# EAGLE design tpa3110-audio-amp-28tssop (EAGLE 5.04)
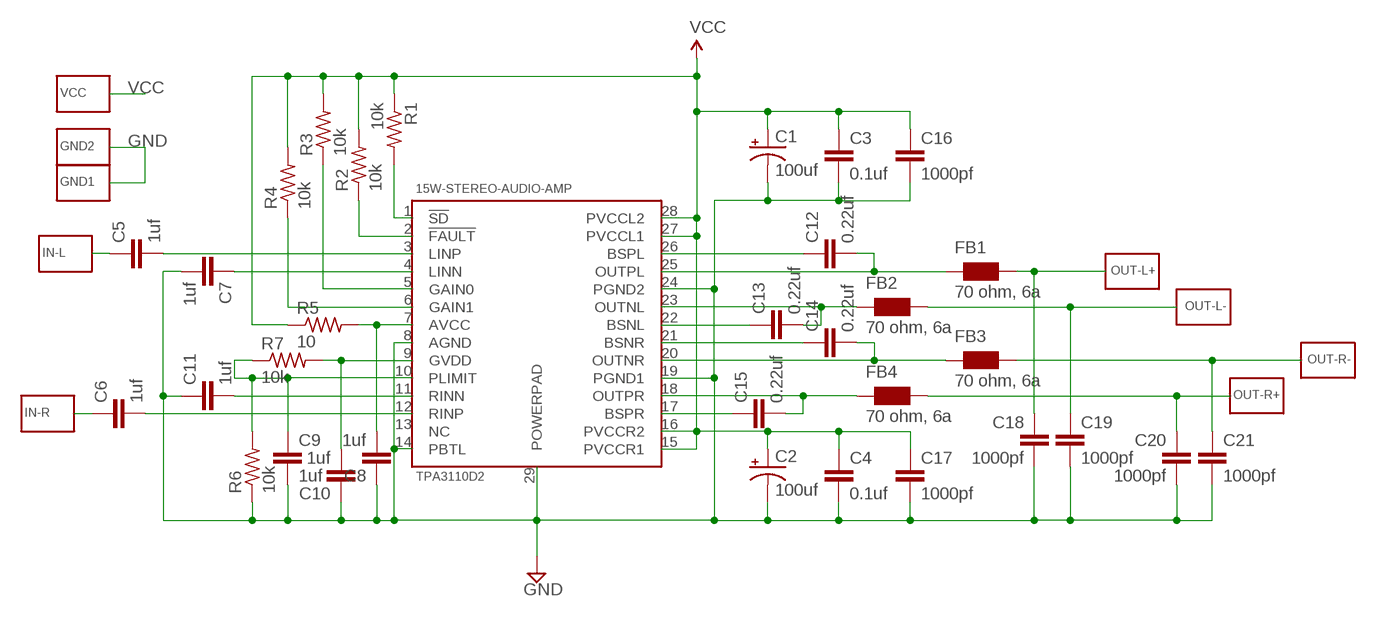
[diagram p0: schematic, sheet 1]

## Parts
15W-STEREO-AUDIO-AMP  TPA3110D2  [TSSOP28]
C1  100uf  CPOL-USE2.5-7  [E2,5-7]
C2  100uf  CPOL-USE2.5-7  [E2,5-7]
C3  0.1uf  C-EUC1210  [C1210]
C4  0.1uf  C-EUC1210  [C1210]
C5  1uf  C-EUC1210  [C1210]
C6  1uf  C-EUC1210  [C1210]
C7  1uf  C-EU050-024X044  [C050-024X044]
C8  1uf  C-EUC1210  [C1210]
C9  1uf  C-EUC1210  [C1210]
C10  1uf  C-EUC1210  [C1210]
C11  1uf  C-EUC1210  [C1210]
C12  0.22uf  C-EUC1210  [C1210]
C13  0.22uf  C-EUC1210  [C1210]
C14  0.22uf  C-EUC1210  [C1210]
C15  0.22uf  C-EUC1210  [C1210]
C16  1000pf  C-EUC1210  [C1210]
C17  1000pf  C-EUC1210  [C1210]
C18  1000pf  C-EUC1210  [C1210]
C19  1000pf  C-EUC1210  [C1210]
C20  1000pf  C-EUC1210  [C1210]
C21  1000pf  C-EUC1210  [C1210]
FB1  70 ohm, 6a  WE-CBF_1812  [1812]
FB2  70 ohm, 6a  WE-CBF_1812  [1812]
FB3  70 ohm, 6a  WE-CBF_1812  [1812]
FB4  70 ohm, 6a  WE-CBF_1812  [1812]
GND1  WIREPAD-SMD-NO-VALUE  [WIREPAD-SMD]
GND2  WIREPAD-SMD-NO-VALUE  [WIREPAD-SMD]
IN-L  WIREPAD-SMD-NO-VALUE  [WIREPAD-SMD]
IN-R  WIREPAD-SMD-NO-VALUE  [WIREPAD-SMD]
OUT-L+  WIREPAD-SMD-NO-VALUE  [WIREPAD-SMD]
OUT-L-  WIREPAD-SMD-NO-VALUE  [WIREPAD-SMD]
OUT-R+  WIREPAD-SMD-NO-VALUE  [WIREPAD-SMD]
OUT-R-  WIREPAD-SMD-NO-VALUE  [WIREPAD-SMD]
R1  10k  R-US_R1210  [R1210]
R2  10k  R-US_R1210  [R1210]
R3  10k  R-US_R1210  [R1210]
R4  10k  R-US_R1210  [R1210]
R5  10  R-US_R1210  [R1210]
R6  10k  R-US_R1210  [R1210]
R7  10k  R-US_R1210  [R1210]
VCC  WIREPAD-SMD-NO-VALUE  [WIREPAD-SMD]

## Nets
GND: 15W-STEREO-AUDIO-AMP.8(AGND) 15W-STEREO-AUDIO-AMP.14(PBTL) 15W-STEREO-AUDIO-AMP.19(PGND1) 15W-STEREO-AUDIO-AMP.24(PGND2) 15W-STEREO-AUDIO-AMP.29(POWERPAD) C1.- C2.- C3.2 C4.2 C7.2 C8.1 C9.2 C10.1 C11.1 C16.2 C17.2 C18.2 C19.2 C20.2 C21.2 GND1.1(P) GND2.1(P) R6.1
N$1: 15W-STEREO-AUDIO-AMP.7(AVCC) C8.2 R5.2
N$2: C5.1 IN-L.1(P)
N$3: 15W-STEREO-AUDIO-AMP.1(!SD) R1.2
N$4: 15W-STEREO-AUDIO-AMP.2(!FAULT) R2.1
N$5: 15W-STEREO-AUDIO-AMP.3(LINP) C5.2
N$6: 15W-STEREO-AUDIO-AMP.11(RINN) C11.2
N$7: 15W-STEREO-AUDIO-AMP.4(LINN) C7.1
N$8: 15W-STEREO-AUDIO-AMP.5(GAIN0) R3.1
N$9: 15W-STEREO-AUDIO-AMP.6(GAIN1) R4.1
N$10: C6.1 IN-R.1(P)
N$11: 15W-STEREO-AUDIO-AMP.12(RINP) C6.2
N$12: 15W-STEREO-AUDIO-AMP.26(BSPL) C12.1
N$13: 15W-STEREO-AUDIO-AMP.25(OUTPL) C12.2 FB1.1
N$14: 15W-STEREO-AUDIO-AMP.22(BSNL) C13.1
N$15: 15W-STEREO-AUDIO-AMP.23(OUTNL) C13.2 FB2.1
N$16: 15W-STEREO-AUDIO-AMP.21(BSNR) C14.1
N$17: 15W-STEREO-AUDIO-AMP.20(OUTNR) C14.2 FB3.1
N$18: 15W-STEREO-AUDIO-AMP.17(BSPR) C15.1
N$19: 15W-STEREO-AUDIO-AMP.18(OUTPR) C15.2 FB4.1
N$20: C20.1 FB4.2 OUT-R+.1(P)
N$21: C21.1 FB3.2 OUT-R-.1(P)
N$22: C19.1 FB2.2 OUT-L-.1(P)
N$23: C18.1 FB1.2 OUT-L+.1(P)
N$25: 15W-STEREO-AUDIO-AMP.10(PLIMIT) C9.1 R6.2 R7.1
N$27: 15W-STEREO-AUDIO-AMP.9(GVDD) C10.2 R7.2
VCC: 15W-STEREO-AUDIO-AMP.15(PVCCR1) 15W-STEREO-AUDIO-AMP.16(PVCCR2) 15W-STEREO-AUDIO-AMP.27(PVCCL1) 15W-STEREO-AUDIO-AMP.28(PVCCL2) C1.+ C2.+ C3.1 C4.1 C16.1 C17.1 R1.1 R2.2 R3.2 R4.2 R5.1 VCC.1(P)
Unconnected: 15W-STEREO-AUDIO-AMP.13(NC)

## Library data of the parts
15W-STEREO-AUDIO-AMP = trl:TPA3110D2
C1 C2 = rcl:CPOL-US: POLARIZED CAPACITOR, American symbol
C3-C21 = rcl:C-EU: CAPACITOR, European symbol
FB1-FB4 = wuerth-elektronik:WE-CBF: SMD EMI Suppression Ferrite Beads
GND1 GND2 IN-L IN-R OUT-L+ OUT-L- OUT-R+ OUT-R- VCC = trl:WIREPAD-SMD-NO-VALUE
R1-R7 = resistor:R-US_: RESISTOR, American symbol

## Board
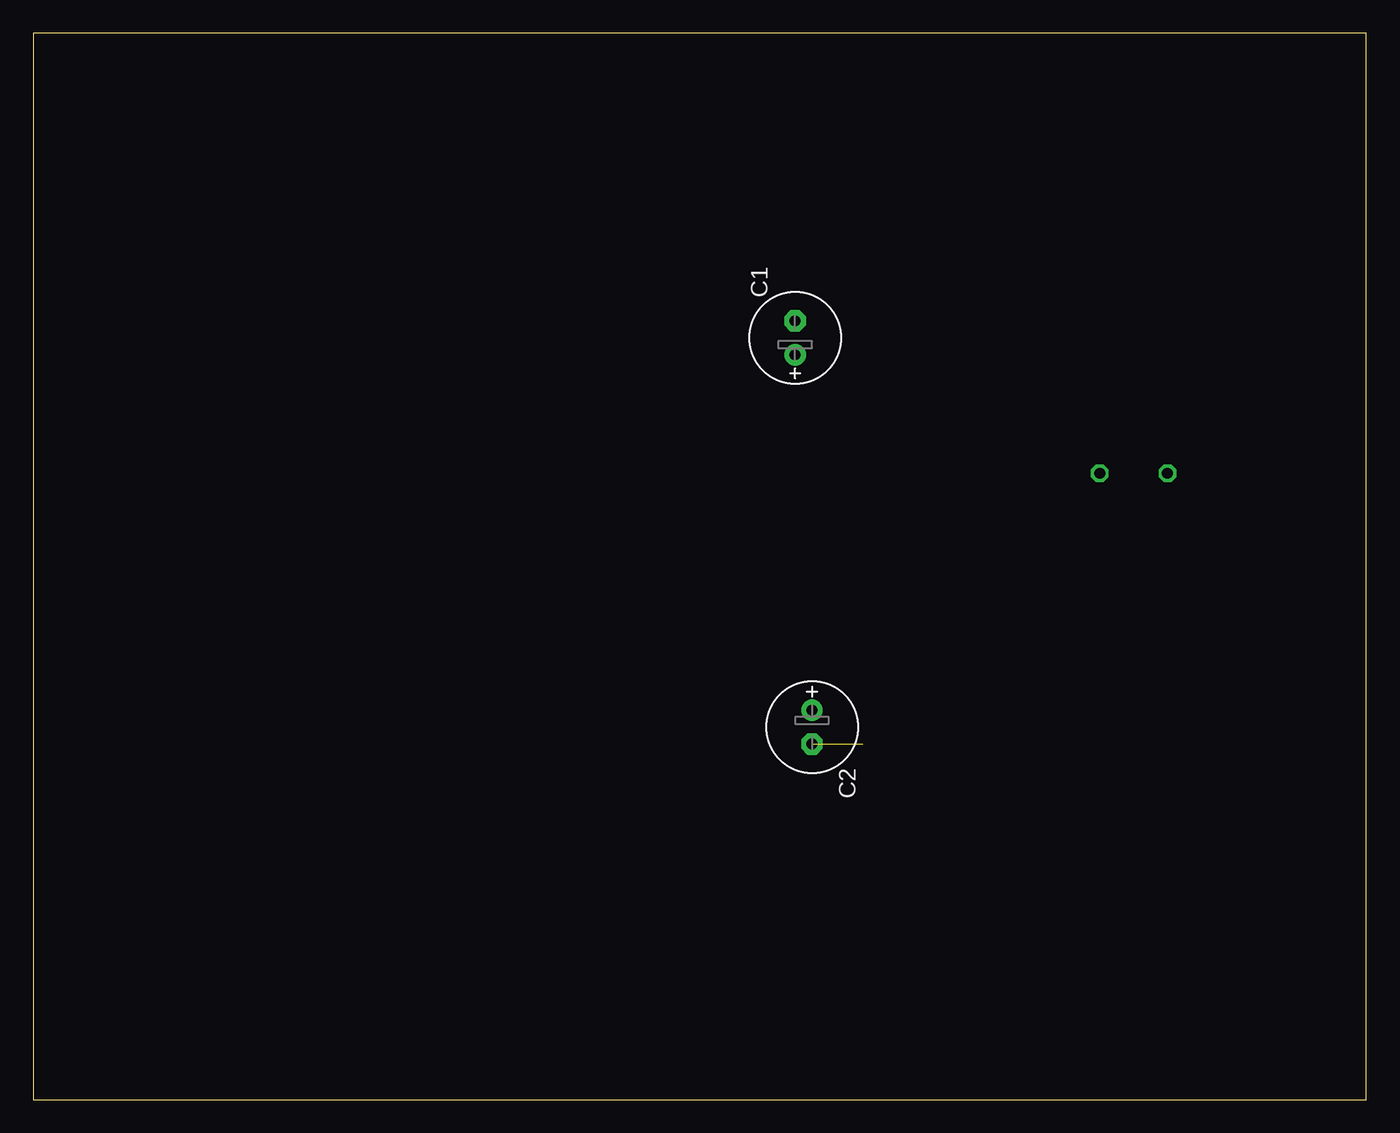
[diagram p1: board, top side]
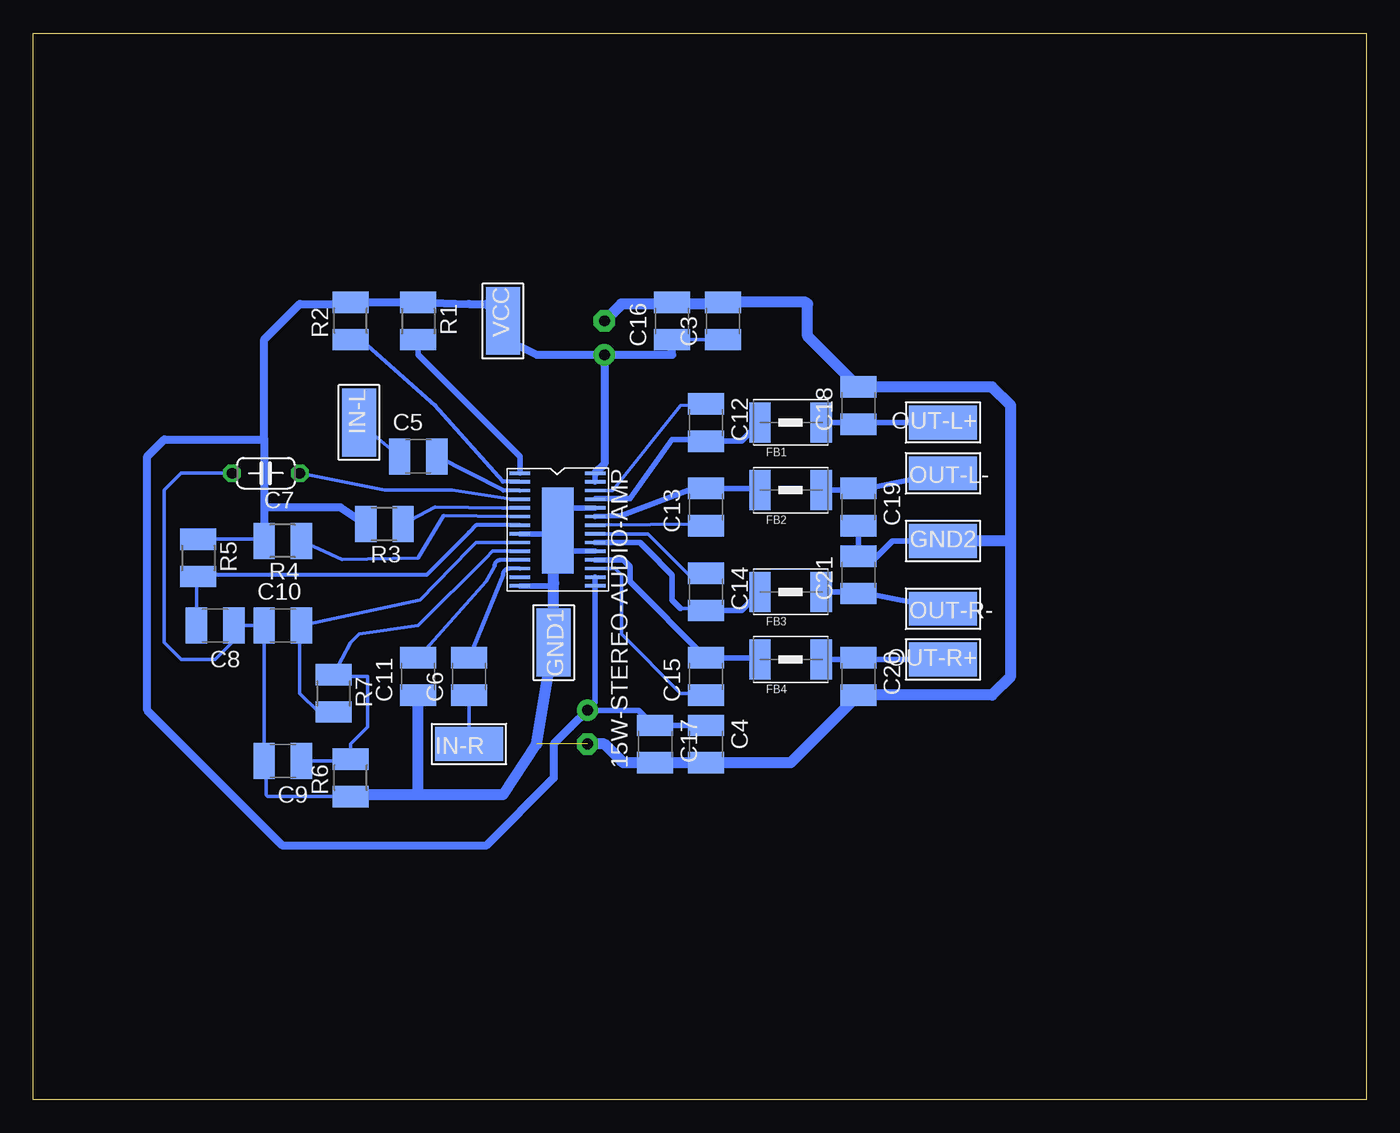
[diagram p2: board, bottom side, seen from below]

Size 100 x 80 mm. Coordinates in mm from the lower left corner, seen from the top.
Outline: 0,0 100,0 100,80 0,80 0,0
Copper layers (1*16): Top 0.035mm / dielectric 1.5mm / Bottom 0.035mm
Design rules "default": minimum track width 10mil, minimum drill 24mil, track to track 8mil, track to pad 8mil, pad to pad 8mil, via to via 8mil, smd to smd 8mil, copper to edge 40mil, drill to drill 8mil, minimum pad ring 10mil, minimum via ring 8mil, stop-mask expansion 4mil, vias tented up to drill 0mil, thermal gap 10mil

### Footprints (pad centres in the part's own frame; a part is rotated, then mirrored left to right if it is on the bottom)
TSSOP28 = smd 0.25 x 1.55: 1 0,0; 2 0.65,0; 3 1.3,0; 4 1.95,0; 5 2.6,0; 6 3.25,0; 7 3.9,0; 8 4.55,0; 9 5.2,0; 10 5.85,0; 11 6.5,0; 12 7.15,0; 13 7.8,0; 14 8.45,0; 15 8.45,5.65; 16 7.8,5.65; 17 7.15,5.65; 18 6.5,5.65; 19 5.85,5.65; 20 5.2,5.65; 21 4.55,5.65; 22 3.9,5.65; 23 3.25,5.65; 24 2.6,5.65; 25 1.95,5.65; 26 1.3,5.65; 27 0.65,5.65; 28 0,5.65 | smd 6.46 x 2.35: 29 4.3,2.85
E2,5-7 = drill 0.813 pad 1.6 round: + -1.27,0 | drill 0.813 pad 1.6 octagon: - 1.27,0
C1210 = smd 1.6 x 2.7: 1 -1.4,0; 2 1.4,0
C050-024X044 = drill 0.813 octagon: 1 -2.54,0; 2 2.54,0
1812 = smd 1.6 x 3: 1 -2.3,0; 2 2.3,0
WIREPAD-SMD = smd 2.54 x 5.08: 1 0,0
R1210 = smd 1.6 x 2.7: 1 -1.4,0; 2 1.4,0

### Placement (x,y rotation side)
15W-STEREO-AUDIO-AMP  63.5,46.99 270 bottom
C1  57.15,57.15 90 top
C2  58.42,27.94 270 top
C3  48.26,58.42 90 bottom
C4  49.53,26.67 270 bottom
C5  71.12,48.26 0 bottom
C6  67.31,31.75 90 bottom
C7  82.55,46.99 180 bottom
C8  86.36,35.56 180 bottom
C9  81.28,25.4 180 bottom
C10  81.28,35.56 0 bottom
C11  71.12,31.75 90 bottom
C12  49.53,50.8 270 bottom
C13  49.53,44.45 90 bottom
C14  49.53,38.1 270 bottom
C15  49.53,31.75 90 bottom
C16  52.07,58.42 90 bottom
C17  53.34,26.67 270 bottom
C18  38.1,52.07 90 bottom
C19  38.1,44.45 270 bottom
C20  38.1,31.75 270 bottom
C21  38.1,39.37 90 bottom
FB1  43.18,50.8 0 bottom
FB2  43.18,45.72 0 bottom
FB3  43.18,38.1 0 bottom
FB4  43.18,33.02 0 bottom
GND1  60.96,34.29 0 bottom
GND2  31.75,41.91 90 bottom
IN-L  75.56,50.8 180 bottom
IN-R  67.31,26.67 270 bottom
OUT-L+  31.75,50.8 90 bottom
OUT-L-  31.75,46.99 270 bottom
OUT-R+  31.75,33.02 90 bottom
OUT-R-  31.75,36.83 270 bottom
R1  71.12,58.42 270 bottom
R2  76.2,58.42 90 bottom
R3  73.66,43.18 180 bottom
R4  81.28,41.91 180 bottom
R5  87.63,40.64 270 bottom
R6  76.2,24.13 90 bottom
R7  77.47,30.48 270 bottom
VCC  64.77,58.42 180 bottom

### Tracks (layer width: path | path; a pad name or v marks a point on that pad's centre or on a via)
GND  (1 unrouted)
  Bottom 0.254: 15W-STEREO-AUDIO-AMP.29 60.65,42.44 | C10.1 82.42,35.56 C10.1 | C10.1 C8.1 84.96,34.42 86.36,33.02 88.9,33.02 90.17,34.29 90.17,45.72 88.9,46.99 C7.2 | 41.91,59.69 42.04,59.82 | 52.07,59.69 C16.2 | 60.9,44.39 60.96,44.45 60.96,43 15W-STEREO-AUDIO-AMP.29 | C21.2 37.97,40.64 36.83,40.64 | 55.75,25.27 55.88,25.4 | 76.07,22.86 R6.1 | R6.1 71.25,22.73 71.12,22.86 | R6.1 82.42,22.73 82.55,22.86 82.55,25.27 C9.2 C10.1 | 15W-STEREO-AUDIO-AMP.29 60.96,42.38 60.96,40.64 60.46,41.14 | 60.96,38.73 61.16,38.54 | 48.39,59.69 49.53,59.69 C3.2 48.39,59.69
  Bottom 0.406: 60.65,42.44 15W-STEREO-AUDIO-AMP.8 | C21.2 C19.2 | 60.9,44.39 15W-STEREO-AUDIO-AMP.24 | 36.83,40.64 35.56,41.91 GND2.1 | 60.46,41.14 15W-STEREO-AUDIO-AMP.19 | 61.16,38.54 15W-STEREO-AUDIO-AMP.14
  Bottom 0.813: 41.91,59.69 41.91,57.28 C18.2 28.07,53.47 26.67,52.07 26.67,41.91 | 49.53,59.69 52.07,59.69 | C1.- 55.88,59.69 53.21,59.69 C16.2 | 42.04,59.82 C3.2 | 26.67,41.91 26.67,39.37 26.67,31.75 28.07,30.35 C20.2 43.18,25.27 C4.2 C17.2 55.75,25.27 | 55.88,25.4 57.15,26.67 C2.- | 71.12,22.86 64.77,22.86 62.23,26.67 GND1.1 60.96,38.73 60.96,40.64 | 71.12,22.86 76.07,22.86 | 71.12,22.86 C11.1 | 26.67,41.91 GND2.1
N$1
  Bottom 0.254: R5.2 87.76,39.11 C8.2
  Bottom 0.305: 15W-STEREO-AUDIO-AMP.7 66.77,43.09 67.31,42.55 70.48,39.37 87.5,39.37 R5.2
N$2
  Bottom 0.254: C5.1 IN-L.1
N$3
  Bottom 0.406: R1.2 71.12,55.88 63.5,48.26 15W-STEREO-AUDIO-AMP.1
N$4
  Bottom 0.254: 75.56,57.15 R2.1 | 15W-STEREO-AUDIO-AMP.2 63.52,46.35
  Bottom 0.305: 63.52,46.35 64.77,46.35 69.85,52.07 75.56,57.15
N$5
  Bottom 0.305: 15W-STEREO-AUDIO-AMP.3 64.74,45.69 arc90 64.77,45.72 C5.2
N$6
  Bottom 0.254: 65.41,40.01 66.04,38.87 C11.2
  Bottom 0.305: 15W-STEREO-AUDIO-AMP.11 64.92,40.49 arc-90 65.41,40.01
N$7
  Bottom 0.254: 15W-STEREO-AUDIO-AMP.4 64.18,45.04 68.58,45.72 73.66,45.72 C7.1
N$8
  Bottom 0.254: 15W-STEREO-AUDIO-AMP.5 64.83,44.39 69.85,44.45 R3.1
N$9
  Bottom 0.254: 15W-STEREO-AUDIO-AMP.6 64.21,43.74 69.22,43.81 71.12,40.64 76.83,40.51 R4.1
N$10
  Bottom 0.254: C6.1 IN-R.1
N$11
  Bottom 0.305: 15W-STEREO-AUDIO-AMP.12 64.3,39.84 arc-90 64.77,39.37 C6.2
N$12
  Bottom 0.254: 15W-STEREO-AUDIO-AMP.26 56.55,45.69 56.52,45.72 51.44,52.07 C12.1
N$13
  Bottom 0.254: 57.8,45.09 15W-STEREO-AUDIO-AMP.25 | 50.8,49.53 50.67,49.4 C12.2
  Bottom 0.406: 57.8,45.09 55.24,45.09 52.07,49.53 50.8,49.53 | C12.2 46.88,49.4 FB1.1
N$14
  Bottom 0.254: 15W-STEREO-AUDIO-AMP.22 49.53,43.18 C13.1
N$15
  Bottom 0.254: C13.2 50.8,45.72 | FB2.1 45.61,45.85
  Bottom 0.406: 15W-STEREO-AUDIO-AMP.23 55.88,43.81 50.8,45.72 | 45.61,45.85 C13.2
N$16
  Bottom 0.254: 15W-STEREO-AUDIO-AMP.21 53.87,42.44 52.07,40.64 50.8,39.37 49.66,39.37 C14.1
N$17
  Bottom 0.254: 51.44,36.83 49.66,36.83 C14.2
  Bottom 0.406: 15W-STEREO-AUDIO-AMP.20 54.49,41.79 53.98,41.27 52.07,39.37 52.07,37.47 51.44,36.83 | C14.2 46.88,36.7 FB3.1
N$18
  Bottom 0.254: 15W-STEREO-AUDIO-AMP.17 56.35,39.84 55.88,39.37 55.88,38.1 55.88,34.92 51.44,30.48 49.66,30.48 C15.1
N$19
  Bottom 0.254: FB4.1 45.61,33.15
  Bottom 0.406: 45.61,33.15 C15.2 55.24,38.87 55.24,40.01 55.73,40.49 15W-STEREO-AUDIO-AMP.18
N$20
  Bottom 0.254: 38.23,33.02 C20.1 37.97,33.02
  Bottom 0.406: 38.23,33.02 FB4.2 | OUT-R+.1 37.97,33.02
N$21
  Bottom 0.254: 37.97,38.1 C21.1 38.23,38.1
  Bottom 0.406: OUT-R-.1 37.97,38.1 | 38.23,38.1 FB3.2
N$22
  Bottom 0.254: 37.97,45.72 C19.1 38.23,45.72
  Bottom 0.406: OUT-L-.1 37.97,45.72 | 38.23,45.72 FB2.2
N$23
  Bottom 0.254: 38.23,50.8 C18.1 37.97,50.8
  Bottom 0.406: 38.23,50.8 FB1.2 | OUT-L+.1 37.97,50.8
N$25
  Bottom 0.254: 15W-STEREO-AUDIO-AMP.10 65.54,41.14 66.04,40.64 71.12,35.56 75.56,34.92 76.2,34.29 R7.1 77.34,31.75 74.93,31.75 74.93,27.94 76.2,26.67 R6.2 76.33,25.4 C9.1
N$27
  Bottom 0.254: 15W-STEREO-AUDIO-AMP.9 66.8,41.79 67.31,41.27 70.99,37.47 C10.2 80.01,35.43 80.01,30.48 78.61,29.08 R7.2
VCC
  Bottom 0.254: C3.1 51.94,57.02 52.07,57.15 C16.1 | R4.2 82.81,42.04 R5.1 | 15W-STEREO-AUDIO-AMP.27 57.85,46.42 | 15W-STEREO-AUDIO-AMP.16 15W-STEREO-AUDIO-AMP.15 | C17.1 53.34,27.94 | 76.33,59.69 R2.2 | 82.68,44.32 82.55,44.45 | C2.+ 57.85,29.78
  Bottom 0.406: 15W-STEREO-AUDIO-AMP.28 15W-STEREO-AUDIO-AMP.27 | C4.1 C17.1 | 53.34,27.94 54.61,29.21 C2.+ | R4.2 82.68,44.32 | 57.85,29.78 15W-STEREO-AUDIO-AMP.16
  Bottom 0.61: R2.2 R1.1 67.31,59.69 66.04,59.69 VCC.1 64.77,57.15 62.23,55.88 C1.+ | C1.+ 57.15,47.69 15W-STEREO-AUDIO-AMP.28 | C1.+ 52.07,55.88 C16.1 | 82.68,49.53 82.68,57.02 81.28,58.42 80.01,59.69 76.33,59.69 | 82.68,49.53 R4.2 | 82.55,44.45 76.97,44.45 R3.2 | C2.+ 59.69,27.94 60.96,26.67 60.96,24.13 66.04,19.05 81.28,19.05 91.44,29.21 91.44,48.26 90.17,49.53 82.68,49.53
